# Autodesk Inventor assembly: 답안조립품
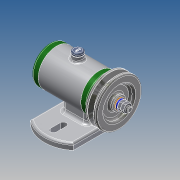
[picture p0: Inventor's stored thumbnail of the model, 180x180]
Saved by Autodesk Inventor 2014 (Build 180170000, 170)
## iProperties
Created: 2017-12
Part Number: 답안조립품
Document SubType Name: Assembly
Designer: kb542-16
Author: kb542-16
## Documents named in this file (14)
- C:\Users\kb542-16\Desktop\471207V1004\답안조립품.iam
- C:\Users\kb542-16\Desktop\471207V1004\1-본체.ipt
- C:\Users\kb542-16\Desktop\471207V1004\축.ipt
- C:\Users\kb542-16\Desktop\471207V1004\키 3 x 3 x 12.ipt
- C:\Users\kb542-16\Desktop\471207V1004\베어링 15 x 32 x 9.ipt
- C:\Users\kb542-16\Desktop\471207V1004\뒤커버.ipt
- C:\Users\kb542-16\Desktop\471207V1004\앞커버.ipt
- C:\Users\kb542-16\Desktop\471207V1004\오일 실 15 25 7.ipt
- C:\Users\kb542-16\Desktop\471207V1004\볼트 M4 x 12.ipt
- C:\Users\kb542-16\Desktop\471207V1004\고무캡.ipt
- C:\Users\kb542-16\Desktop\471207V1004\V벨트풀리.ipt
- C:\Users\kb542-16\Desktop\471207V1004\와셔 8x17.ipt
- C:\Users\kb542-16\Desktop\471207V1004\너트 M 8.ipt
- C:\Users\kb542-16\Desktop\471207V1004\스프링와셔 8.ipt
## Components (3 placed, 3 different names)
1. 1-본체:1
2. 고무캡:1
3. V벨트풀리:1 — 각도:2
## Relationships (1: Angle 1)
- 각도:2 [Angle]: V벨트풀리:1
